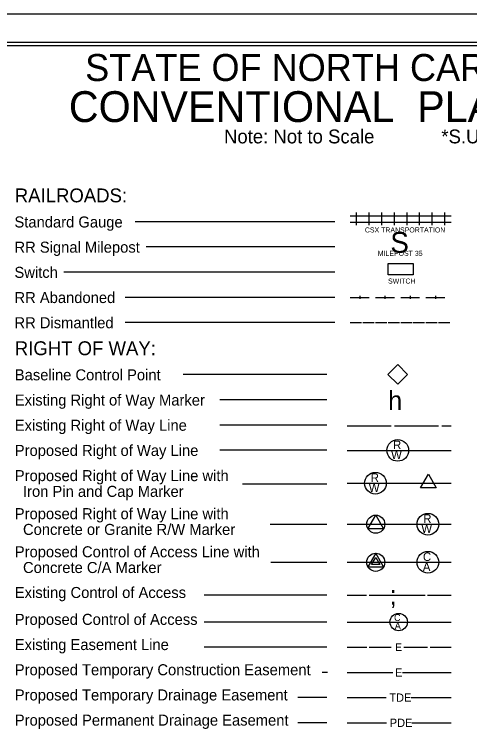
# Model space of a CAD drawing. Extents: x 1729679 to 1731363, y 539860 to 540960.
# Drawn here: x 1730240 to 1730602, y 540392 to 540960 of the extents above; entities that cross this region are included whole.
import ezdxf

# ---------------------------------------------------------------- set-up
doc = ezdxf.new("R2010")
doc.units = 0
for name, color, linetype in [('Default', 7, 'Continuous'), ('Sheet Plot Border Inside CELL', 7, 'Continuous'), ('Sheet Plot Border Outside CELL', 7, 'Continuous'), ('Sheet Symbology CELL', 7, 'Continuous')]:
    doc.layers.add(name, color=color, linetype=linetype)

msp = doc.modelspace()

# ---------------------------------------------------------------- linework, layer by layer
at = {"layer": 'Default'}
msp.add_lwpolyline([(1730536.9, 540674.45), (1730544.72, 540682.27), (1730552.54, 540674.45), (1730544.72, 540666.62)], close=True, dxfattribs=at)
at = {"layer": 'Sheet Plot Border Inside CELL'}
msp.add_lwpolyline([(1729692.08, 539882.79), (1731358.58, 539882.79), (1731358.58, 540937.89), (1729692.08, 540937.89)], close=True, dxfattribs=at)
at = {"layer": 'Sheet Plot Border Outside CELL'}
msp.add_lwpolyline([(1729679.08, 539860.34), (1731363.08, 539860.34), (1731363.08, 540960.34), (1729679.08, 540960.34)], close=True, dxfattribs=at)
at = {"layer": 'Sheet Symbology CELL'}
for p, q in [((1730512.08, 540792.87), (1730512.08, 540802.87)), ((1730522.08, 540792.87), (1730522.08, 540802.87)), ((1730532.08, 540792.87), (1730532.08, 540802.87)), ((1730542.08, 540792.87), (1730542.08, 540802.87)), ((1730552.08, 540792.87), (1730552.08, 540802.87)), ((1730562.08, 540792.87), (1730562.08, 540802.87)), ((1730572.08, 540792.87), (1730572.08, 540802.87)), ((1730582.08, 540792.87), (1730582.08, 540802.87)), ((1730494.68, 540795.6), (1730336.27, 540795.6)), ((1730507.08, 540800.37), (1730517.08, 540800.37)), ((1730507.08, 540795.37), (1730517.08, 540795.37)), ((1730517.08, 540800.37), (1730527.08, 540800.37)), ((1730517.08, 540795.37), (1730527.08, 540795.37)), ((1730527.08, 540800.37), (1730537.08, 540800.37)), ((1730527.08, 540795.37), (1730537.08, 540795.37)), ((1730537.08, 540800.37), (1730547.08, 540800.37)), ((1730537.08, 540795.37), (1730547.08, 540795.37)), ((1730547.08, 540800.37), (1730557.08, 540800.37)), ((1730547.08, 540795.37), (1730557.08, 540795.37)), ((1730557.08, 540800.37), (1730567.08, 540800.37)), ((1730557.08, 540795.37), (1730567.08, 540795.37)), ((1730567.08, 540800.37), (1730577.08, 540800.37)), ((1730567.08, 540795.37), (1730577.08, 540795.37)), ((1730577.08, 540800.37), (1730587.08, 540800.37)), ((1730577.08, 540795.37), (1730587.08, 540795.37)), ((1730494.68, 540775.6), (1730345.13, 540775.6)), ((1730494.68, 540755.6), (1730279.77, 540755.6)), ((1730494.68, 540735.6), (1730328.52, 540735.6)), ((1730507.08, 540735.6), (1730522.08, 540735.6)), ((1730514.58, 540736.85), (1730514.58, 540734.35)), ((1730527.08, 540735.6), (1730542.08, 540735.6)), ((1730534.58, 540736.85), (1730534.58, 540734.35)), ((1730547.08, 540735.6), (1730562.08, 540735.6)), ((1730554.58, 540736.85), (1730554.58, 540734.35)), ((1730567.08, 540735.6), (1730582.08, 540735.6)), ((1730574.58, 540736.85), (1730574.58, 540734.35)), ((1730494.68, 540715.6), (1730328.52, 540715.6)), ((1730494.68, 540715.6), (1730328.52, 540715.6)), ((1730507.08, 540715.6), (1730516.08, 540715.6)), ((1730517.08, 540715.6), (1730526.08, 540715.6)), ((1730527.08, 540715.6), (1730536.08, 540715.6)), ((1730537.08, 540715.6), (1730546.08, 540715.6)), ((1730547.08, 540715.6), (1730556.08, 540715.6)), ((1730557.08, 540715.6), (1730566.08, 540715.6)), ((1730567.08, 540715.6), (1730576.08, 540715.6)), ((1730577.08, 540715.6), (1730586.08, 540715.6)), ((1730488.55, 540674.25), (1730374.33, 540674.25)), ((1730488.55, 540654.25), (1730403.61, 540654.25)), ((1730488.55, 540634.25), (1730403.61, 540634.25)), ((1730504.58, 540633.68), (1730539.58, 540633.68)), ((1730542.08, 540633.68), (1730577.08, 540633.68)), ((1730579.58, 540633.68), (1730587.08, 540633.68)), ((1730488.55, 540614.25), (1730403.61, 540614.25)), ((1730504.58, 540614.13), (1730587.08, 540614.13)), ((1730488.55, 540587.4), (1730421.43, 540587.4)), ((1730504.58, 540588), (1730587.08, 540588)), ((1730569.03, 540588), (1730569.03, 540588)), ((1730488.55, 540555.37), (1730443.56, 540555.37)), ((1730504.58, 540555.5), (1730587.08, 540555.5)), ((1730527.28, 540555.5), (1730527.28, 540555.5)), ((1730488.55, 540525.12), (1730443.93, 540525.12)), ((1730504.58, 540525.26), (1730587.08, 540525.26)), ((1730527.28, 540525.26), (1730527.28, 540525.26)), ((1730488.55, 540499.18), (1730391, 540499.18)), ((1730504.58, 540499.18), (1730520.04, 540499.18)), ((1730522.04, 540499.18), (1730566.45, 540499.18)), ((1730568.45, 540499.18), (1730587.08, 540499.18)), ((1730488.55, 540477.83), (1730391, 540477.83)), ((1730504.58, 540477.83), (1730587.08, 540477.83)), ((1730488.55, 540457.83), (1730391, 540457.83)), ((1730504.58, 540457.83), (1730520.09, 540457.83)), ((1730522.09, 540457.83), (1730539.59, 540457.83)), ((1730549.59, 540457.83), (1730568.34, 540457.83)), ((1730570.34, 540457.83), (1730587.08, 540457.83)), ((1730488.93, 540437.83), (1730484.76, 540437.83)), ((1730504.58, 540437.83), (1730507.19, 540437.83)), ((1730507.19, 540437.83), (1730540.94, 540437.83)), ((1730548.44, 540437.83), (1730582.19, 540437.83)), ((1730582.19, 540437.83), (1730587.08, 540437.83)), ((1730488.55, 540417.83), (1730465.4, 540417.83)), ((1730504.58, 540417.83), (1730507.93, 540417.83)), ((1730507.93, 540417.83), (1730535.43, 540417.83)), ((1730555.43, 540417.83), (1730582.93, 540417.83)), ((1730582.93, 540417.83), (1730587.08, 540417.83)), ((1730488.55, 540397.83), (1730465.4, 540397.83)), ((1730504.58, 540397.83), (1730508.38, 540397.83)), ((1730508.38, 540397.83), (1730535.88, 540397.83)), ((1730555.88, 540397.83), (1730583.38, 540397.83)), ((1730583.38, 540397.83), (1730587.08, 540397.83))]:
    msp.add_line(p, q, dxfattribs=at)
for points in [[(1731346.08, 540935.34), (1729846.08, 540935.34), (1729846.08, 539886.35), (1731346.08, 539886.35)], [(1730537.08, 540762.57), (1730557.08, 540762.57), (1730557.08, 540753.47), (1730537.08, 540753.47)], [(1730562.78, 540584.4), (1730569.03, 540595.2), (1730575.28, 540584.4)], [(1730521.03, 540551.9), (1730527.28, 540562.7), (1730533.53, 540551.9)], [(1730521.03, 540521.66), (1730533.53, 540521.66), (1730527.28, 540532.46)], [(1730524.01, 540523.38), (1730527.28, 540529.02), (1730530.54, 540523.38)]]:
    msp.add_lwpolyline(points, close=True, dxfattribs=at)
for centre, radius in [((1730544.7, 540614.13), 8.61), ((1730527, 540588), 8.61), ((1730527.27, 540555.5), 7.2), ((1730568.67, 540555.5), 8.61), ((1730568.67, 540525.26), 8.61), ((1730527.27, 540525.26), 7.2), ((1730545.45, 540477.83), 6.89)]:
    msp.add_circle(centre, radius, dxfattribs=at)

# ---------------------------------------------------------------- texts
for s, height, p in [('STATE OF NORTH CAROLINA, DIVISION OF HIGHWAYS', 21.419, (1730296.64, 540907.38)), ('CONVENTIONAL  PLAN SHEET SYMBOLS', 24.4803, (1730283.69, 540874.81)), ('RAILROADS:', 11, (1730240.8, 540811.05)), ('Standard Gauge', 8.75, (1730240.52, 540791.08)), ('S', 16.5, (1730538.84, 540770.98)), ('RR Signal Milepost', 8.75, (1730240.52, 540771.08)), ('Switch', 8.75, (1730240.52, 540751.08)), ('RR Abandoned', 8.75, (1730240.52, 540731.08)), ('RR Dismantled', 8.75, (1730240.52, 540711.08)), ('RIGHT OF WAY:', 11, (1730240.8, 540689.7)), ('Baseline Control Point', 8.75, (1730240.8, 540669.7)), ('Existing Right of Way Marker', 8.75, (1730240.8, 540649.7)), ('h', 15, (1730537.09, 540646.18)), ('Existing Right of Way Line', 8.75, (1730240.8, 540629.7)), ('R', 6.75, (1730540.99, 540615.14)), ('Proposed Right of Way Line', 8.75, (1730240.8, 540609.7)), ('W', 6.75, (1730539.45, 540607.19)), ('Proposed Right of Way Line with', 8.75, (1730240.8, 540589.7)), ('R', 6.75, (1730523.29, 540589.02)), ('  Iron Pin and Cap Marker', 8.75, (1730240.8, 540577.2)), ('W', 6.75, (1730521.75, 540581.07)), ('Proposed Right of Way Line with', 8.75, (1730240.8, 540559.48)), ('R', 6.75, (1730564.96, 540556.52)), ('  Concrete or Granite R/W Marker', 8.75, (1730240.8, 540546.98)), ('W', 6.75, (1730563.43, 540548.57)), ('Proposed Control of Access Line with', 8.75, (1730240.8, 540529.23)), ('C', 6.75, (1730564.71, 540526.27)), ('  Concrete C/A Marker', 8.75, (1730240.8, 540516.73)), ('A', 6.75, (1730564.65, 540518.32)), ('Existing Control of Access', 8.75, (1730240.8, 540496.91)), (';', 15, (1730538.33, 540491.68)), ('Proposed Control of Access', 8.75, (1730240.8, 540475.56)), ('C', 5.4, (1730541.79, 540478.64)), ('A', 5.4, (1730542.33, 540472.15)), ('Existing Easement Line', 8.75, (1730240.8, 540455.56)), ('E', 6, (1730542.79, 540454.83)), ('Proposed Temporary Construction Easement', 8.75, (1730240.8, 540435.56)), ('E', 6.55, (1730542.54, 540434.53)), ('Proposed Temporary Drainage Easement', 8.75, (1730240.8, 540415.56)), ('TDE', 6.55, (1730538.03, 540414.53)), ('Proposed Permanent Drainage Easement', 8.75, (1730240.8, 540395.56)), ('PDE', 6.55, (1730538.38, 540394.53))]:
    msp.add_text(s, height=height, dxfattribs=at).set_placement(p)
for s, height, p in [('Note: Not to Scale', 11, (1730406.82, 540857.85)), ('*S.U.E. = Subsurface Utility Engineering', 11, (1730579.3, 540857.85)), ('CSX TRANSPORTATION', 4, (1730518.64, 540787.13)), ('MILEPOST 35', 4, (1730528.83, 540768.55)), ('SWITCH', 4, (1730537.03, 540746.55))]:
    msp.add_text(s, height=height, rotation=360, dxfattribs=at).set_placement(p)

doc.saveas('drawing.dxf')
